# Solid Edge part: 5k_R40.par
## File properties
Author: Türk
Template: Iso Part.par
Last saved by: Türk
Revision: 10
Application: Solid Edge
Accuracy: 0,990
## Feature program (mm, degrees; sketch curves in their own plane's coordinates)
pattern "PatternOccurrence_2"  XOffset = 7.2 deg
pattern "PatternOccurrence_3"  XCount = 50; XOffset = 7.2 deg
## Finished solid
Body 1: solid body, 303 faces, 902 edges, 600 vertices.
  Faces by surface: plane 202, cylinder 101
  Edges by curve: line 700, circle 202
Bounding box of the edges (mm): 88.000 x 30.000 x 87.886, from (-44, 0, -43.9429) to (44, 30, 43.9429).
Cylindrical faces by radius (mm): R14 x1, R40 x50, R44 x50
Planar faces by outward normal: +y 1, -y 1, oblique 200
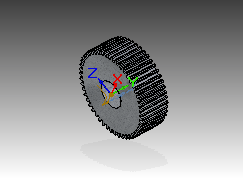
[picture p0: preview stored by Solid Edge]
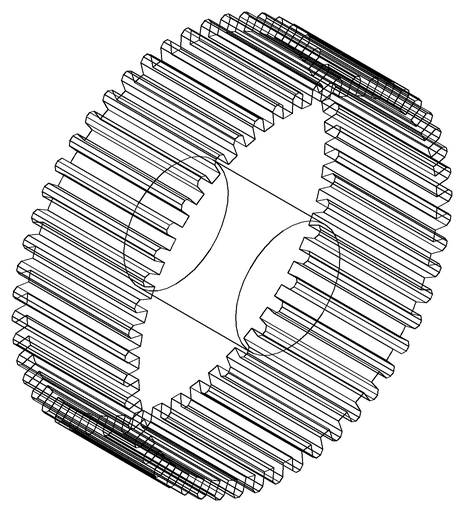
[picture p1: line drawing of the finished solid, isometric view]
